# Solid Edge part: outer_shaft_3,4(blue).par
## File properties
Author: vinurabandara
Template: iso metric part.par
Last saved by: Nimesh.N
Revision: 11
Application: Solid Edge
Density: 7833.000 kg/m^3
Accuracy: 0.990
Username: Nimesh.N
Material: Steel
Face Style: Steel
Fill Style: ANSI32(Steel)
Virtual Style: Machined steel
Grouping: Metals\Steel
LibraryName: Materials
Coef. of Thermal Exp: 1.3e-05
Thermal Conductivity: 32.0
Specific Heat: 481.0
Modulus of Elasticity: 199947953000.0
Poisson's Ratio: 0.29
Yield Stress: 262000766.0
Ultimate Stress: 358527364.0
Elongation: 0.0
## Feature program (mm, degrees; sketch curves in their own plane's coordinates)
sketch for "unnamed Protrusion 1" #1 plane through (0, 0, 0) normal (0, -1, 0) x-axis (1, 0, 0)
  circle centre (0, 0) radius 12.5
sketch for "unnamed Protrusion 1" #2 plane through (0, 0, 0) normal (0, -1, 0) x-axis (1, 0, 0)
  circle centre (0, 0) radius 7.5
extrude "unnamed Protrusion 1" add finite 142.5 along +normal
sketch for "ExtrudedProtrusion_2" #1 plane through (0, -142.5, 0) normal (0, -1, 0) x-axis (1, 0, 0)
  circle centre (0, 0) radius 7.5
sketch for "ExtrudedProtrusion_2" #2 plane through (0, -142.5, 0) normal (0, -1, 0) x-axis (1, 0, 0)
  circle centre (0, 0) radius 17.5
extrude "ExtrudedProtrusion_2" add finite 40 along +normal
sketch for "ExtrudedProtrusion_3" #1 plane through (0, 0, 0) normal (0, 1, 0) x-axis (0, 0, -1)
  circle centre (0, 0) radius 7.5
sketch for "ExtrudedProtrusion_3" #2 plane through (0, 0, 0) normal (0, 1, 0) x-axis (0, 0, -1)
  circle centre (0, 0) radius 17.5
extrude "ExtrudedProtrusion_3" add finite 30 along +normal
sketch for "ExtrudedCutout_4" plane through (0, 0, 7.6) normal (0, 0, 1) x-axis (1, 0, 0)
extrude "ExtrudedCutout_4" cut through along +normal  Profile_Plane1_Distance = 7.6 mm
sketch for "ExtrudedCutout_5" plane through (1.6449, 0, -7.4198) normal (-0.21644, 0, 0.976296) x-axis (0.976296, 0, 0.21644)
extrude "ExtrudedCutout_5" cut through along -normal  Profile_Plane1_Distance = 7.6 mm
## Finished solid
Body 1: solid body, 15 faces, 22 edges, 8 vertices.
  Faces by surface: plane 10, cylinder 5
  Edges by curve: circle 11, line 10, intersection 1
Bounding box of the edges (mm): 35.000 x 212.500 x 35.000, from (-17.5, -182.5, -17.5) to (17.5, 30, 17.5).
Cylindrical faces by radius (mm): R6 x1, R7.5 x1, R12.5 x1, R17.5 x2
Planar faces by outward normal: +y 3, +z 1, -y 3, oblique 3
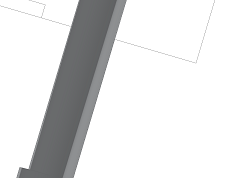
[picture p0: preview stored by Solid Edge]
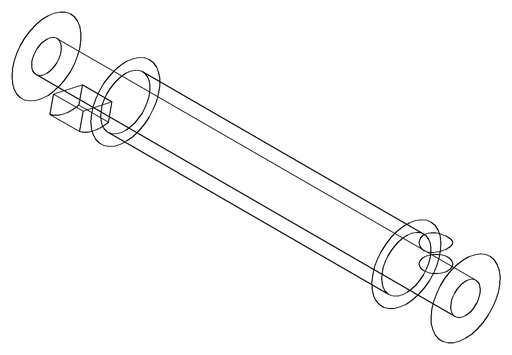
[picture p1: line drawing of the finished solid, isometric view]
